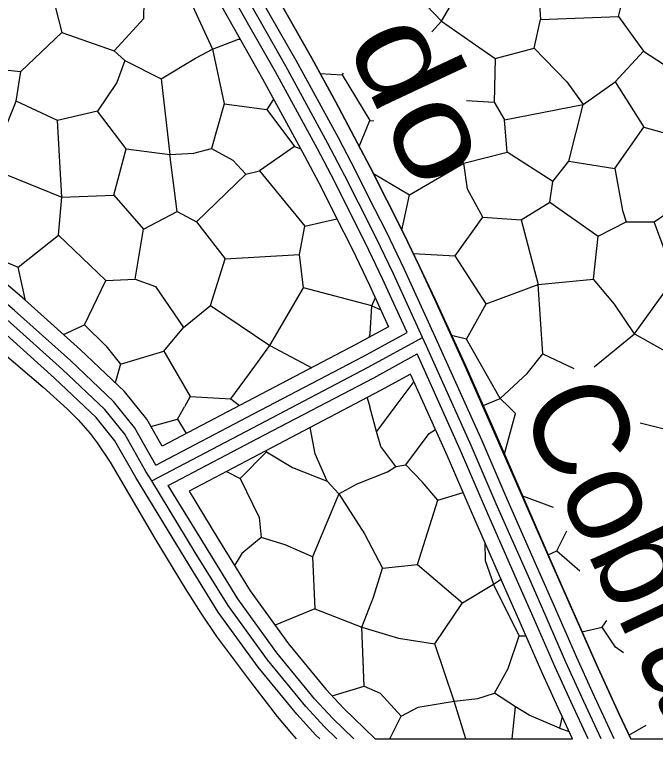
# Model space of a CAD drawing. Extents: x -64005 to -55000, y -89025 to -80000.
# Drawn here: x -62360 to -61817, y -89025 to -88387 of the extents above; entities that cross this region are included whole.
import ezdxf
from ezdxf.enums import TextEntityAlignment as Align

# ---------------------------------------------------------------- set-up
doc = ezdxf.new("R2010")
doc.units = 0
doc.header["$LTSCALE"] = 32
doc.linetypes.add('LONG_DASHED', pattern=[7.5, 6, -1.5])
for name, color, linetype, lineweight in [('19', 7, 'Continuous', 25), ('31', 7, 'Continuous', 25), ('39', 7, 'LONG_DASHED', 25), ('7', 7, 'Continuous', 13), ('8', 7, 'Continuous', 25)]:
    doc.layers.add(name, color=color, linetype=linetype, lineweight=lineweight)

msp = doc.modelspace()

# ---------------------------------------------------------------- linework, layer by layer
at = {"layer": '19'}
for p, q in [((-62006.75, -88401.12), (-61998.36, -88392.14)), ((-61977.18, -88459.28), (-61953.88, -88460.87)), ((-62068.06, -88498.34), (-62059.12, -88476.29)), ((-62265.41, -88500.36), (-62228.42, -88504.93)), ((-62350.76, -88628.67), (-62357, -88600.37)), ((-61960.62, -88631.4), (-61916.45, -88615.08)), ((-62057.5, -88633.16), (-62054.48, -88626.57)), ((-62057.5, -88633.16), (-62049.91, -88636.52)), ((-62143.88, -88666.9), (-62108.36, -88685.59)), ((-61912.62, -88673.7), (-61886.31, -88686.23)), ((-62021.91, -88697.16), (-62037.94, -88718.73)), ((-62061.39, -88710.96), (-62059.21, -88718.73)), ((-61948.73, -88711.58), (-61941.48, -88718.73)), ((-62222.01, -88729.27), (-62214.66, -88741.37)), ((-62001.44, -88797.66), (-61980.13, -88791.33)), ((-61903.68, -88803.94), (-61929.7, -88794.22)), ((-61900.68, -88840.74), (-61881.16, -88857.55)), ((-62105.76, -88889.59), (-62139.27, -88903.61)), ((-61932.64, -88912.68), (-61926.97, -88912.45)), ((-61977.72, -88999.78), (-61987.69, -88967.76)), ((-61938.48, -88999.78), (-61935.75, -88972.65)), ((-62042.09, -88999.79), (-62032.51, -88980.63)), ((-61839.74, -88996.55), (-61825.22, -88988.26)), ((-61898.46, -88990.86), (-61890.32, -88993.62))]:
    msp.add_line(p, q, dxfattribs=at)
for points in [[(-62361.02, -88148.88), (-62348.42, -88161.5), (-62332.41, -88178.38), (-62310.52, -88203.6), (-62294.47, -88222.57), (-62275.24, -88246.71), (-62249.96, -88279.59), (-62215.97, -88328.31), (-62203.19, -88348.57), (-62188.49, -88372.84), (-62171.32, -88403.56), (-62149.92, -88441.13), (-62114.33, -88506.21), (-62100.17, -88533.4), (-62088.82, -88556.09), (-62073.86, -88585.55), (-62059.49, -88615.65), (-62043.32, -88650.88)], [(-62234.98, -88752.06), (-62248.02, -88729.05), (-62267, -88705.72), (-62304.13, -88670.41), (-62351.69, -88627.84), (-62411.55, -88576.82), (-62494.57, -88503.96), (-62543.23, -88459.51), (-62600.48, -88406.83), (-62615.11, -88393.33), (-62638.89, -88375.88), (-62677.57, -88357.31), (-62721.51, -88340.97), (-62813.78, -88310.94), (-62886.97, -88287.85), (-62917.54, -88277.03)], [(-62051.2, -88342.8), (-62030.5, -88358.22), (-61998.36, -88392.14), (-61972.82, -88348.09), (-61968.86, -88312.85), (-61962.69, -88292.58)], [(-61838.23, -88999.77), (-61848.07, -88978.81), (-61867.18, -88936.88), (-61904.37, -88852.55), (-61953.33, -88739.82), (-61978.23, -88683.64), (-62003.83, -88627.76), (-62016.98, -88599.98), (-62030.69, -88571.74), (-62058.93, -88515.66), (-62088.19, -88460.13), (-62108.22, -88423.39), (-62149.46, -88350.57), (-62155.05, -88340.93)], [(-62155.05, -88340.93), (-62149.46, -88350.57), (-62108.22, -88423.39), (-62088.19, -88460.13), (-62058.93, -88515.66), (-62030.69, -88571.74), (-62016.98, -88599.98), (-62003.83, -88627.76), (-61978.23, -88683.64), (-61953.33, -88739.82), (-61904.37, -88852.55), (-61867.18, -88936.88), (-61848.07, -88978.81), (-61838.23, -88999.77), (-61599.09, -88999.74)], [(-62328.82, -88367.47), (-62320.01, -88401.84), (-62275.54, -88417.26), (-62250.44, -88389.95), (-62250.01, -88361.3), (-62267.17, -88351.17)], [(-61916.45, -88362.19), (-61914.7, -88390.82), (-61848.64, -88388.18), (-61838.51, -88347.21)], [(-62214.33, -88367.91), (-62192.32, -88415.94), (-62170.3, -88407.56), (-62169.19, -88407.3)], [(-61848.64, -88388.18), (-61827.51, -88417.69), (-61810.33, -88428.71), (-61781.06, -88413.73)], [(-61998.36, -88392.14), (-61953, -88423.85), (-61919.98, -88415.05), (-61914.7, -88390.82)], [(-62401.92, -88430.03), (-62354.8, -88434.87), (-62320.01, -88401.84)], [(-62275.54, -88417.26), (-62266.73, -88425.62), (-62235.9, -88441.04), (-62206.84, -88423.41), (-62192.32, -88415.94)], [(-62192.32, -88415.94), (-62182.62, -88462.19), (-62146.31, -88467.03)], [(-61919.98, -88415.05), (-61892.23, -88443.69), (-61878.58, -88462.63), (-61851.28, -88443.69), (-61827.51, -88417.69)], [(-62266.73, -88425.62), (-62273.33, -88444.13), (-62289.62, -88468.36), (-62323.52, -88476.29), (-62358.75, -88459.99)], [(-61953, -88423.85), (-61953.88, -88460.87), (-61945.07, -88475.86), (-61878.58, -88462.63)], [(-62449.92, -88465.27), (-62421.72, -88496.55), (-62396.18, -88493.03), (-62367.57, -88482.45), (-62358.75, -88459.99), (-62354.8, -88434.87)], [(-62235.9, -88441.04), (-62228.42, -88504.93), (-62208.16, -88504.04), (-62193.19, -88500.08)], [(-62101.15, -88436.36), (-62082.46, -88437.51), (-62081.44, -88436.22)], [(-62082.46, -88437.51), (-62059.12, -88476.29), (-62055.83, -88476.64)], [(-61851.28, -88443.69), (-61827.07, -88482.02), (-61791.62, -88491.72)], [(-62140.61, -88458.16), (-62146.31, -88467.03), (-62122.97, -88498.32), (-62117.61, -88500.22)], [(-62182.62, -88462.19), (-62193.19, -88500.08), (-62175.14, -88509.77), (-62164.13, -88521.67), (-62152.48, -88519.03)], [(-61904.13, -88527.84), (-61890.47, -88510.66), (-61878.58, -88462.63)], [(-62320.01, -88541.33), (-62275.97, -88539.56), (-62265.41, -88500.36), (-62289.62, -88468.36)], [(-62369.33, -88521.06), (-62320.01, -88541.33), (-62323.52, -88476.29)], [(-61986.76, -88506.41), (-61979.42, -88512.42), (-61942.87, -88503.17), (-61945.07, -88475.86)], [(-61890.47, -88510.66), (-61851.72, -88516.82), (-61827.07, -88482.02)], [(-62122.97, -88498.32), (-62152.48, -88519.03), (-62114.17, -88565.73), (-62087.03, -88559.62)], [(-62275.97, -88539.56), (-62250.88, -88568.21), (-62222.26, -88553.23), (-62228.42, -88504.93)], [(-61963.56, -88558.23), (-61930.98, -88560.44), (-61906.77, -88545.47), (-61904.13, -88527.84), (-61942.87, -88503.17)], [(-62056.12, -88521.23), (-62025.65, -88539.3), (-61979.42, -88512.42)], [(-62022.34, -88588.94), (-61986.91, -88590.84), (-61963.56, -88558.23), (-61976.35, -88534.44), (-61979.42, -88512.42)], [(-61851.72, -88516.82), (-61845.12, -88552.51), (-61842.04, -88562.21), (-61818.26, -88562.21), (-61778.42, -88534.9)], [(-62222.26, -88553.23), (-62205.96, -88562.04), (-62164.13, -88521.67)], [(-62399.72, -88582.75), (-62357, -88600.37), (-62322.65, -88573.5), (-62320.01, -88541.33)], [(-62032.05, -88569.04), (-62030.94, -88563.97), (-62025.65, -88539.3)], [(-61906.77, -88545.47), (-61865.81, -88574.09), (-61842.04, -88562.21)], [(-62205.96, -88562.04), (-62181.75, -88593.32), (-62118.77, -88589.8), (-62114.17, -88565.73)], [(-61930.98, -88560.44), (-61916.45, -88615.08), (-61869.77, -88610.67), (-61865.81, -88574.09)], [(-61835.13, -88656.96), (-61800.77, -88609.36), (-61818.26, -88562.21)], [(-62322.65, -88573.5), (-62282.59, -88611.82), (-62257.93, -88610.51), (-62250.88, -88568.21)], [(-62257.93, -88610.51), (-62240.75, -88616.68), (-62216.96, -88651.47), (-62194.08, -88632.97), (-62181.75, -88593.32)], [(-62194.08, -88632.97), (-62143.88, -88666.9), (-62115.26, -88617.99), (-62118.77, -88589.8)], [(-61977.35, -88661.36), (-61960.62, -88631.4), (-61986.91, -88590.84)], [(-62318.58, -88657.48), (-62300.64, -88649.28), (-62282.59, -88611.82)], [(-61869.26, -88684.94), (-61835.13, -88656.96), (-61851.86, -88631.85), (-61869.77, -88610.67)], [(-62059.61, -88659.78), (-62058.82, -88656.96), (-62057.5, -88633.16), (-62115.26, -88617.99)], [(-61948.73, -88711.58), (-61925.83, -88690.44), (-61912.62, -88673.7), (-61916.45, -88615.08)], [(-61835.13, -88656.96), (-61800.4, -88676.33), (-61759.01, -88678.54), (-61752.41, -88652.55), (-61748.89, -88624.78)], [(-62300.64, -88649.28), (-62282.59, -88667.09), (-62270.24, -88682.51), (-62274.83, -88698.28)], [(-62270.24, -88682.51), (-62233.7, -88671.49), (-62216.96, -88651.47)], [(-62043.32, -88650.88), (-62070.91, -88665.96), (-62163.01, -88714.22), (-62234.98, -88752.06)], [(-61963.15, -88717.66), (-61948.73, -88711.58), (-61977.35, -88661.36), (-61989.85, -88658.27)], [(-62176.9, -88712.03), (-62161.05, -88690.44), (-62143.88, -88666.9)], [(-62233.7, -88671.49), (-62211.24, -88709.83), (-62216.17, -88718.73)], [(-62024.63, -88691.11), (-62050.01, -88705), (-62142.44, -88753.44), (-62212.21, -88790.1)], [(-61887.45, -88999.77), (-61899.62, -88973.65), (-61913.23, -88943.9), (-61932.95, -88898.74), (-61943.88, -88873.91), (-61972.26, -88809.63), (-61993.44, -88760.39), (-62024.63, -88691.11)], [(-62211.24, -88709.83), (-62176.9, -88712.03), (-62169.5, -88717.63)], [(-62244.52, -88735.23), (-62222.01, -88729.27), (-62216.17, -88718.73)], [(-62037.94, -88718.73), (-62053.38, -88739.48), (-62059.21, -88718.73)], [(-61945.17, -88758.61), (-61935.75, -88724.37), (-61941.48, -88718.73)], [(-61830.18, -88732.16), (-61803.03, -88739.04), (-61806.81, -88718.73)], [(-62095.23, -88781.67), (-62105.45, -88758.58), (-62109.43, -88737.71), (-62109.28, -88736.06)], [(-62085.47, -88792.33), (-62069.93, -88783.89), (-62044.19, -88773.67), (-62037.09, -88769.23), (-62028.65, -88767.9), (-62009, -88741.26), (-62003.59, -88737.84)], [(-62037.09, -88769.23), (-62049.83, -88752.36), (-62053.38, -88739.48)], [(-62168.92, -88779.46), (-62146.73, -88756.8), (-62146.96, -88755.82)], [(-62146.73, -88756.8), (-62124.53, -88770.12), (-62095.23, -88781.67), (-62085.47, -88792.33), (-62107.68, -88845.62), (-62130.74, -88835.4), (-62151.16, -88829.19)], [(-62180.46, -88773.42), (-62168.92, -88779.46), (-62152.93, -88812.31), (-62151.16, -88829.19), (-62167.59, -88842.96), (-62173.69, -88852.97)], [(-62085.47, -88792.33), (-62063.58, -88826.07), (-62048.5, -88855.39), (-62018.75, -88852.28), (-62001.44, -88797.66), (-62014.77, -88782.12), (-62028.65, -88767.9)], [(-62212.21, -88790.1), (-62187.76, -88830.18), (-62160.46, -88874.4), (-62127.95, -88919.22)], [(-61908.12, -88843.92), (-61900.68, -88840.74), (-61892.36, -88823.57)], [(-61961.72, -88833.51), (-61961.49, -88848.73), (-61954.38, -88868.72), (-61947.94, -88864.71)], [(-62107.68, -88845.62), (-62105.76, -88889.59), (-62065.8, -88905.13), (-62056.05, -88879.82), (-62048.5, -88855.39)], [(-62018.75, -88852.28), (-61980.58, -88884.71), (-61954.38, -88868.72)], [(-61987.69, -88967.76), (-61967.71, -88965.54), (-61953.5, -88961.1), (-61941.96, -88940.22), (-61932.64, -88912.68), (-61954.38, -88868.72)], [(-62065.8, -88905.13), (-62034.73, -88914.47), (-62004.1, -88919.35), (-61980.58, -88884.71)], [(-61879.46, -88909.04), (-61862.5, -88905.14), (-61858.54, -88899.67)], [(-62091.1, -88963.38), (-62064.02, -88955.31), (-62065.8, -88905.13)], [(-61844.25, -88927.01), (-61850.97, -88922.02), (-61862.5, -88905.14)], [(-62127.95, -88919.22), (-62096.44, -88957.58), (-62081.47, -88973.86), (-62054.73, -88999.79), (-61887.45, -88999.77)], [(-62064.02, -88955.31), (-62050.27, -88961.1), (-62032.51, -88980.63), (-62018.31, -88973.09), (-61987.69, -88967.76), (-62004.1, -88919.35)], [(-61896.26, -88980.87), (-61898.46, -88990.86), (-61924.2, -88979.75), (-61935.75, -88972.65), (-61953.5, -88961.1)]]:
    msp.add_lwpolyline(points, dxfattribs=at)
at = {"layer": '39'}
for points in [[(-62014.49, -88660.02), (-62039.21, -88606.16), (-62053.78, -88575.66), (-62068.83, -88546.02), (-62080.22, -88523.21), (-62094.57, -88495.66), (-62130.37, -88430.22), (-62151.82, -88392.56), (-62169.14, -88361.57), (-62184.14, -88336.8), (-62197.3, -88315.92), (-62231.89, -88266.35), (-62257.6, -88232.91), (-62277.15, -88208.34), (-62293.53, -88189.02), (-62315.81, -88163.33), (-62332.36, -88145.88), (-62346.42, -88131.81), (-62363.48, -88119.4)], [(-62243.87, -88781.4), (-62248.75, -88773.41), (-62266.67, -88741.78), (-62283.54, -88721.04), (-62319.4, -88686.95), (-62366.5, -88644.79), (-62426.26, -88593.83), (-62509.58, -88520.73), (-62558.44, -88476.09), (-62615.73, -88423.38), (-62629.44, -88410.73), (-62650.52, -88395.26), (-62686.39, -88378.04), (-62728.92, -88362.23), (-62820.65, -88332.36), (-62894.12, -88309.19), (-62932.2, -88295.7)], [(-62243.87, -88781.4), (-62152.86, -88733.58), (-62060.59, -88685.23), (-62014.49, -88660.02)], [(-61863.12, -88999.77), (-61879.59, -88964.4), (-61893.09, -88934.89), (-61912.74, -88889.87), (-61923.7, -88865), (-61952.02, -88800.81), (-61973.25, -88751.5), (-62011.14, -88667.31), (-62014.49, -88660.02)], [(-62087.06, -88999.79), (-62097.61, -88989.56), (-62113.43, -88972.34), (-62145.77, -88932.98), (-62179.16, -88886.94), (-62206.93, -88841.95), (-62243.87, -88781.4)]]:
    msp.add_lwpolyline(points, dxfattribs=at)
at = {"layer": '7'}
msp.add_line((-61838.23, -88999.77), (-61599.09, -88999.74), dxfattribs=at)
at = {"layer": '7', "lineweight": 25}
for points in [[(-61838.23, -88999.77), (-61848.07, -88978.81), (-61867.21, -88936.89), (-61904.57, -88852.64), (-61953.72, -88740.01), (-61978.59, -88683.81), (-62004, -88627.84), (-62016.98, -88599.98), (-62030.55, -88571.68), (-62058.78, -88515.64), (-62088.21, -88460.22), (-62108.34, -88423.54), (-62149.46, -88350.57), (-62159.29, -88333.72), (-62179.9, -88300.6), (-62180.64, -88299.46)], [(-62444.21, -88607.9), (-62407.73, -88639.95), (-62372.63, -88670.72), (-62335.79, -88701.92), (-62315.56, -88720.32), (-62305.89, -88730.06), (-62296.04, -88741.24), (-62289.98, -88749.1), (-62279.01, -88765.6), (-62241.31, -88830.17), (-62215.54, -88872.48), (-62202.31, -88893.44), (-62188.89, -88913.21), (-62160.28, -88951.51), (-62137.47, -88980.96), (-62125.59, -88995.26), (-62121.48, -88999.8)]]:
    msp.add_lwpolyline(points, dxfattribs=at)
at = {"layer": '8', "linetype": 'LONG_DASHED'}
for points in [[(-62027.46, -88655.71), (-62048.27, -88610.4), (-62062.75, -88580.08), (-62077.76, -88550.52), (-62089.13, -88527.76), (-62103.39, -88500.37), (-62139.1, -88435.09), (-62160.53, -88397.47), (-62177.78, -88366.61), (-62192.65, -88342.06), (-62205.64, -88321.45), (-62239.96, -88272.26), (-62265.48, -88239.08), (-62284.88, -88214.7), (-62301.12, -88195.53), (-62323.22, -88170.05), (-62339.53, -88152.86), (-62352.94, -88139.43), (-62368.97, -88127.77)], [(-62101.43, -88999.79), (-62104.78, -88996.55), (-62120.98, -88978.91), (-62153.69, -88939.09), (-62187.47, -88892.51), (-62215.45, -88847.18), (-62257.37, -88778.48), (-62274.96, -88747.44), (-62290.89, -88727.85), (-62326.18, -88694.3), (-62373.08, -88652.32)], [(-62240.22, -88768.19), (-62157.51, -88724.72), (-62065.31, -88676.41), (-62027.46, -88655.71)], [(-61874.15, -88999.77), (-61888.67, -88968.59), (-61902.21, -88938.97), (-61921.9, -88893.89), (-61932.85, -88869.03), (-61961.19, -88804.81), (-61982.41, -88755.53), (-62019.12, -88673.95)]]:
    msp.add_lwpolyline(points, dxfattribs=at)
at = {"layer": '8'}
for points in [[(-62240.22, -88768.19), (-62258.38, -88736.12), (-62276.19, -88714.23), (-62312.62, -88679.6), (-62359.92, -88637.26), (-62419.72, -88586.27), (-62502.91, -88513.28), (-62551.68, -88468.72), (-62608.95, -88416.02), (-62623.07, -88403), (-62645.35, -88386.65), (-62682.47, -88368.83), (-62725.63, -88352.79), (-62817.6, -88322.84), (-62890.94, -88299.7), (-62926.19, -88287.22)], [(-61852.09, -88999.77), (-61870.51, -88960.21), (-61883.96, -88930.81), (-61903.58, -88885.85), (-61914.55, -88860.97), (-61942.85, -88796.81), (-61964.1, -88747.47), (-62002.04, -88663.17), (-62030.15, -88601.92), (-62044.81, -88571.24), (-62059.9, -88541.52), (-62071.31, -88518.66), (-62085.75, -88490.96), (-62121.64, -88425.35), (-62143.11, -88387.65), (-62160.5, -88356.53)], [(-62229.79, -88785.29), (-62148.21, -88742.44), (-62055.87, -88694.05), (-62019.12, -88673.95)], [(-62072.7, -88999.79), (-62090.44, -88982.58), (-62105.88, -88965.78), (-62137.85, -88926.87), (-62170.85, -88881.37), (-62198.41, -88836.72), (-62229.79, -88785.29)]]:
    msp.add_lwpolyline(points, dxfattribs=at)

# ---------------------------------------------------------------- texts
at = {"layer": '31', "width": 1.2}
msp.add_text('do', height=80, rotation=295.154, dxfattribs=at).set_placement((-62049.44, -88474.2), align=Align.CENTER)
at = {"layer": '31'}
msp.add_text('Cobrão', height=80, rotation=295.154, dxfattribs=at).set_placement((-61859.03, -88876.73), align=Align.CENTER)

doc.saveas('drawing.dxf')
